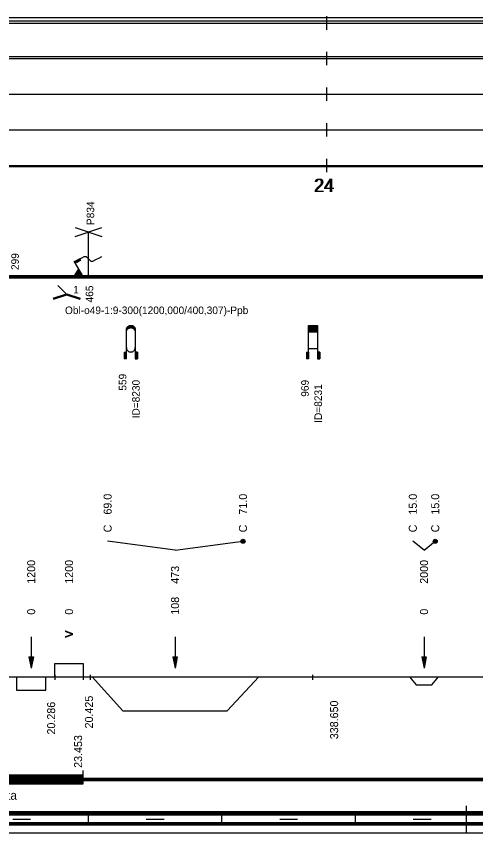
# Model space of a CAD drawing. Extents: x 2 to 10148, y 0 to 380.
# Drawn here: x 2628.8 to 2732, y 0 to 183.5 of the extents above; entities that cross this region are included whole.
import ezdxf

# ---------------------------------------------------------------- set-up
doc = ezdxf.new("R2010")
doc.units = 0
for name, color, linetype in [('CARA_S_OBJEKTY', 7, 'Continuous'), ('KRIV1_CARA', 7, 'Continuous'), ('KRIV1_TEXT', 7, 'Continuous'), ('L_OBJEKTY_TEXT', 7, 'Continuous'), ('L_OBJEKTY_TVAR', 7, 'Continuous'), ('OBJEKTY_TEXT', 7, 'Continuous'), ('OBJEKTY_TVAR', 7, 'Continuous'), ('RAM', 7, 'Continuous'), ('RYCHL_A', 7, 'Continuous'), ('RYCHL_B', 7, 'Continuous'), ('RYCHL_C', 7, 'Continuous'), ('RYCHL_RASTR', 7, 'Continuous'), ('RYCHL_STAN', 7, 'Continuous'), ('STAN_CARA', 7, 'Continuous')]:
    doc.layers.add(name, color=color, linetype=linetype)

msp = doc.modelspace()

# ---------------------------------------------------------------- linework, layer by layer
for p, q in [((2637.43, 35.51), (2637.43, 34.32)), ((2643.79, 35.51), (2643.79, 34.32)), ((2645.42, 35.51), (2645.42, 34.32)), ((2695.33, 35.51), (2695.33, 34.32))]:
    msp.add_line(p, q)
at = {"layer": 'CARA_S_OBJEKTY'}
for p, q in [((2328.7, 125.25), (3155.54, 125.25)), ((2328.7, 125), (3155.54, 125)), ((2328.7, 124.75), (3155.54, 124.75))]:
    msp.add_line(p, q, dxfattribs=at)
at = {"layer": 'KRIV1_CARA'}
for p, q in [((2637.46, 35), (2637.46, 38)), ((2637.46, 38), (2643.81, 38)), ((2643.81, 38), (2643.81, 35)), ((2328.7, 35), (3155.54, 35)), ((2628.83, 35), (2628.83, 32)), ((2635.43, 32), (2635.43, 35)), ((2645.86, 35), (2652.76, 27.39)), ((2676.19, 27.39), (2683.29, 35)), ((2717.16, 35), (2718.66, 33.2)), ((2722.2, 33.2), (2723.7, 35)), ((2718.66, 33.2), (2722.2, 33.2)), ((2628.83, 32), (2635.43, 32)), ((2652.76, 27.39), (2676.19, 27.39))]:
    msp.add_line(p, q, dxfattribs=at)
at = {"layer": 'KRIV1_TEXT'}
for p, q in [((2664.47, 63.5), (2649.31, 65.5)), ((2664.47, 63.5), (2679.74, 65.5)), ((2720.43, 63.5), (2717.91, 65.5)), ((2720.43, 63.5), (2722.95, 65.5)), ((2632.13, 44), (2632.13, 42.2)), ((2664.47, 44), (2664.47, 42.2)), ((2720.43, 44), (2720.43, 42.2)), ((2632.13, 42.2), (2632.13, 40)), ((2664.47, 42.2), (2664.47, 40)), ((2720.43, 42.2), (2720.43, 40)), ((2631.63, 39.5), (2632.13, 37)), ((2631.63, 39.5), (2632.63, 39.5)), ((2631.73, 39.5), (2632.13, 37.5)), ((2631.83, 39.5), (2632.13, 38)), ((2631.93, 39.5), (2632.13, 38.5)), ((2632.03, 39.5), (2632.13, 39)), ((2632.13, 40), (2632.13, 37)), ((2632.63, 39.5), (2632.13, 37)), ((2632.53, 39.5), (2632.13, 37.5)), ((2632.43, 39.5), (2632.13, 38)), ((2632.33, 39.5), (2632.13, 38.5)), ((2632.23, 39.5), (2632.13, 39)), ((2632.13, 39.5), (2632.13, 39.5)), ((2632.13, 39.5), (2632.13, 39.5)), ((2663.97, 39.5), (2664.47, 37)), ((2663.97, 39.5), (2664.97, 39.5)), ((2664.07, 39.5), (2664.47, 37.5)), ((2664.17, 39.5), (2664.47, 38)), ((2664.27, 39.5), (2664.47, 38.5)), ((2664.37, 39.5), (2664.47, 39)), ((2664.47, 40), (2664.47, 37)), ((2664.97, 39.5), (2664.47, 37)), ((2664.87, 39.5), (2664.47, 37.5)), ((2664.77, 39.5), (2664.47, 38)), ((2664.67, 39.5), (2664.47, 38.5)), ((2664.57, 39.5), (2664.47, 39)), ((2664.47, 39.5), (2664.47, 39.5)), ((2664.47, 39.5), (2664.47, 39.5)), ((2719.93, 39.5), (2720.43, 37)), ((2719.93, 39.5), (2720.93, 39.5)), ((2720.03, 39.5), (2720.43, 37.5)), ((2720.13, 39.5), (2720.43, 38)), ((2720.23, 39.5), (2720.43, 38.5)), ((2720.33, 39.5), (2720.43, 39)), ((2720.43, 40), (2720.43, 37)), ((2720.93, 39.5), (2720.43, 37)), ((2720.83, 39.5), (2720.43, 37.5)), ((2720.73, 39.5), (2720.43, 38)), ((2720.63, 39.5), (2720.43, 38.5)), ((2720.53, 39.5), (2720.43, 39)), ((2720.43, 39.5), (2720.43, 39.5)), ((2720.43, 39.5), (2720.43, 39.5))]:
    msp.add_line(p, q, dxfattribs=at)
for centre, radius in [((2679.74, 65.5), 0.45), ((2679.74, 65.5), 0.3), ((2679.74, 65.5), 0.15), ((2722.95, 65.5), 0.45), ((2722.95, 65.5), 0.3), ((2722.95, 65.5), 0.15)]:
    msp.add_circle(centre, radius, dxfattribs=at)
at = {"layer": 'L_OBJEKTY_TVAR'}
for p, q in [((2595.01, 13), (2643.82, 13)), ((2643.82, 11), (2643.82, 14)), ((2595.01, 12.75), (2643.82, 12.75)), ((2595.01, 12.5), (2643.82, 12.5)), ((2595.01, 12.25), (2643.82, 12.25)), ((2595.01, 12), (2643.82, 12)), ((2595.01, 11.75), (2643.82, 11.75)), ((2595.01, 11.5), (2643.82, 11.5)), ((2595.01, 11.25), (2643.82, 11.25)), ((2595.01, 11), (2643.82, 11))]:
    msp.add_line(p, q, dxfattribs=at)
at = {"layer": 'OBJEKTY_TVAR'}
for p, q in [((2642.02, 134), (2648.02, 136)), ((2642.02, 136), (2648.02, 134)), ((2645.02, 125), (2645.02, 135)), ((2643.82, 125), (2641.82, 128.46)), ((2642.02, 128.5), (2643.02, 129)), ((2642.22, 128.1), (2642.02, 128.5)), ((2642.12, 128.3), (2643.12, 128.8)), ((2643.22, 128.6), (2642.22, 128.1)), ((2643.02, 129), (2643.52, 129.25)), ((2643.02, 129), (2643.22, 128.6)), ((2643.52, 129.25), (2644.02, 129.5)), ((2644.02, 129.5), (2644.52, 129.5)), ((2644.52, 129.5), (2645.02, 129)), ((2645.02, 129), (2645.52, 128.5)), ((2645.52, 128.5), (2646.02, 128.5)), ((2646.02, 128.5), (2646.68, 128.83)), ((2646.68, 128.83), (2647.35, 129.17)), ((2647.35, 129.17), (2648.02, 129.5)), ((2641.82, 125), (2642.82, 126.73)), ((2641.97, 125), (2642.89, 126.6)), ((2642.12, 125), (2642.97, 126.47)), ((2642.27, 125), (2643.04, 126.34)), ((2642.42, 125), (2643.12, 126.21)), ((2642.57, 125), (2643.19, 126.08)), ((2642.72, 125), (2643.27, 125.95)), ((2642.87, 125), (2643.34, 125.82)), ((2643.02, 125), (2643.42, 125.69)), ((2643.17, 125), (2643.49, 125.56)), ((2643.32, 125), (2643.57, 125.43)), ((2643.47, 125), (2643.64, 125.3)), ((2643.62, 125), (2643.72, 125.17)), ((2640.11, 121), (2638.11, 123)), ((2637.07, 120.12), (2640.07, 121.12)), ((2640.14, 121.12), (2643.14, 120.12)), ((2637.11, 120), (2640.11, 121)), ((2637.14, 119.89), (2640.14, 120.89)), ((2640.07, 120.89), (2643.07, 119.89)), ((2640.11, 121), (2643.11, 120)), ((2653.79, 113.72), (2653.88, 113.8)), ((2653.87, 113.79), (2655.19, 113.79)), ((2653.88, 113.8), (2654.01, 113.89)), ((2653.93, 113.84), (2655.13, 113.84)), ((2654, 113.89), (2655.06, 113.89)), ((2654.01, 113.89), (2654.14, 113.96)), ((2654.09, 113.94), (2654.97, 113.94)), ((2654.14, 113.96), (2654.17, 113.97)), ((2654.17, 113.97), (2654.29, 114.01)), ((2654.22, 113.99), (2654.84, 113.99)), ((2654.29, 114.01), (2654.43, 114.03)), ((2654.43, 114.03), (2654.54, 114.04)), ((2654.54, 114.04), (2654.67, 114.03)), ((2654.67, 114.03), (2654.8, 114)), ((2654.8, 114), (2654.91, 113.97)), ((2654.91, 113.97), (2655.02, 113.91)), ((2655.02, 113.91), (2655.09, 113.86)), ((2655.09, 113.86), (2655.24, 113.75)), ((2694.49, 106.54), (2694.49, 114.04)), ((2694.49, 114.04), (2696.49, 114.04)), ((2694.49, 113.99), (2696.49, 113.99)), ((2694.49, 113.94), (2696.49, 113.94)), ((2694.49, 113.89), (2696.49, 113.89)), ((2694.49, 113.84), (2696.49, 113.84)), ((2694.49, 113.79), (2696.49, 113.79)), ((2696.49, 114.04), (2696.49, 106.54)), ((2653.53, 113.04), (2653.54, 113.19)), ((2653.53, 113.09), (2653.71, 113.09)), ((2653.53, 106.54), (2653.53, 113.04)), ((2653.53, 113.04), (2653.68, 113.04)), ((2653.53, 112.99), (2653.65, 112.99)), ((2653.53, 112.94), (2653.62, 112.94)), ((2653.53, 112.89), (2653.6, 112.89)), ((2653.53, 112.84), (2653.58, 112.84)), ((2653.53, 112.79), (2653.57, 112.79)), ((2653.53, 112.74), (2653.56, 112.74)), ((2653.53, 112.69), (2653.55, 112.69)), ((2653.53, 112.52), (2653.54, 112.67)), ((2653.53, 112.64), (2653.54, 112.64)), ((2653.54, 113.19), (2653.58, 113.35)), ((2653.54, 113.19), (2653.79, 113.19)), ((2653.54, 113.14), (2653.75, 113.14)), ((2653.54, 112.67), (2653.58, 112.82)), ((2653.55, 113.24), (2653.84, 113.24)), ((2653.56, 113.29), (2653.9, 113.29)), ((2653.58, 113.35), (2653.64, 113.49)), ((2653.58, 113.34), (2653.96, 113.34)), ((2653.58, 112.82), (2653.64, 112.97)), ((2653.59, 113.39), (2654.04, 113.39)), ((2653.61, 113.44), (2654.15, 113.44)), ((2653.64, 113.49), (2653.7, 113.6)), ((2653.64, 113.49), (2654.3, 113.49)), ((2653.64, 112.97), (2653.7, 113.07)), ((2653.66, 113.54), (2655.4, 113.54)), ((2653.69, 113.59), (2655.37, 113.59)), ((2653.7, 113.6), (2653.79, 113.72)), ((2653.7, 113.07), (2653.79, 113.19)), ((2653.73, 113.64), (2655.33, 113.64)), ((2653.77, 113.69), (2655.29, 113.69)), ((2653.79, 113.19), (2653.88, 113.28)), ((2653.82, 113.74), (2655.24, 113.74)), ((2653.88, 113.28), (2654.01, 113.37)), ((2654.01, 113.37), (2654.14, 113.44)), ((2654.14, 113.44), (2654.17, 113.45)), ((2654.17, 113.45), (2654.29, 113.49)), ((2654.29, 113.49), (2654.43, 113.51)), ((2654.43, 113.51), (2654.54, 113.52)), ((2654.54, 113.52), (2654.67, 113.51)), ((2654.67, 113.51), (2654.8, 113.48)), ((2654.76, 113.49), (2655.42, 113.49)), ((2654.8, 113.48), (2654.91, 113.44)), ((2654.91, 113.44), (2655.02, 113.39)), ((2654.91, 113.44), (2655.45, 113.44)), ((2655.02, 113.39), (2655.47, 113.39)), ((2655.02, 113.39), (2655.09, 113.34)), ((2655.09, 113.34), (2655.24, 113.22)), ((2655.1, 113.34), (2655.48, 113.34)), ((2655.16, 113.29), (2655.5, 113.29)), ((2655.22, 113.24), (2655.51, 113.24)), ((2655.24, 113.75), (2655.32, 113.65)), ((2655.24, 113.22), (2655.32, 113.13)), ((2655.27, 113.19), (2655.52, 113.19)), ((2655.31, 113.14), (2655.52, 113.14)), ((2655.32, 113.65), (2655.41, 113.52)), ((2655.32, 113.13), (2655.41, 113)), ((2655.35, 113.09), (2655.53, 113.09)), ((2655.38, 113.04), (2655.53, 113.04)), ((2655.41, 113.52), (2655.45, 113.43)), ((2655.41, 113), (2655.45, 112.91)), ((2655.41, 112.99), (2655.53, 112.99)), ((2655.44, 112.94), (2655.53, 112.94)), ((2655.45, 113.43), (2655.49, 113.31)), ((2655.45, 112.91), (2655.49, 112.78)), ((2655.46, 112.89), (2655.53, 112.89)), ((2655.48, 112.84), (2655.53, 112.84)), ((2655.49, 113.31), (2655.52, 113.19)), ((2655.49, 112.79), (2655.53, 112.79)), ((2655.49, 112.78), (2655.52, 112.67)), ((2655.5, 112.74), (2655.53, 112.74)), ((2655.51, 112.69), (2655.53, 112.69)), ((2655.52, 113.19), (2655.53, 113.1)), ((2655.52, 112.67), (2655.53, 112.57)), ((2655.52, 112.64), (2655.53, 112.64)), ((2655.53, 113.1), (2655.53, 113.04)), ((2655.53, 113.04), (2655.53, 106.54)), ((2655.53, 112.57), (2655.53, 112.52)), ((2694.49, 113.74), (2696.49, 113.74)), ((2694.49, 113.69), (2696.49, 113.69)), ((2694.49, 113.64), (2696.49, 113.64)), ((2694.49, 113.59), (2696.49, 113.59)), ((2694.49, 113.54), (2696.49, 113.54)), ((2694.49, 113.49), (2696.49, 113.49)), ((2694.49, 113.44), (2696.49, 113.44)), ((2694.49, 113.39), (2696.49, 113.39)), ((2694.49, 113.34), (2696.49, 113.34)), ((2694.49, 113.29), (2696.49, 113.29)), ((2694.49, 113.24), (2696.49, 113.24)), ((2694.49, 113.19), (2696.49, 113.19)), ((2694.49, 113.14), (2696.49, 113.14)), ((2694.49, 113.09), (2696.49, 113.09)), ((2694.49, 113.04), (2696.49, 113.04)), ((2694.49, 112.99), (2696.49, 112.99)), ((2694.49, 112.94), (2696.49, 112.94)), ((2694.49, 112.89), (2696.49, 112.89)), ((2694.49, 112.84), (2696.49, 112.84)), ((2694.49, 112.79), (2696.49, 112.79)), ((2694.49, 112.74), (2696.49, 112.74)), ((2694.49, 112.69), (2696.49, 112.69)), ((2694.49, 112.64), (2696.49, 112.64)), ((2694.49, 112.59), (2696.49, 112.59)), ((2653.53, 109.04), (2653.54, 108.89)), ((2653.54, 108.89), (2653.58, 108.74)), ((2653.58, 108.74), (2653.64, 108.59)), ((2653.64, 108.59), (2653.7, 108.49)), ((2653.7, 108.49), (2653.79, 108.37)), ((2653.79, 108.37), (2653.88, 108.28)), ((2653.88, 108.28), (2654.01, 108.19)), ((2655.09, 108.22), (2655.24, 108.34)), ((2655.24, 108.34), (2655.32, 108.44)), ((2655.32, 108.44), (2655.41, 108.56)), ((2655.41, 108.56), (2655.45, 108.65)), ((2655.45, 108.65), (2655.49, 108.78)), ((2655.49, 108.78), (2655.52, 108.89)), ((2655.52, 108.89), (2655.53, 108.99)), ((2655.53, 108.99), (2655.53, 109.04)), ((2694.49, 108.85), (2696.49, 108.85)), ((2653.03, 108.04), (2653.53, 108.04)), ((2653.03, 108.04), (2653.03, 106.54)), ((2653.53, 106.54), (2653.03, 106.54)), ((2653.08, 108.04), (2653.08, 106.54)), ((2653.13, 108.04), (2653.13, 106.54)), ((2653.18, 108.04), (2653.18, 106.54)), ((2653.23, 108.04), (2653.23, 106.54)), ((2653.28, 108.04), (2653.28, 106.54)), ((2653.33, 108.04), (2653.33, 106.54)), ((2653.38, 108.04), (2653.38, 106.54)), ((2653.43, 108.04), (2653.43, 106.54)), ((2653.48, 108.04), (2653.48, 106.54)), ((2654.01, 108.19), (2654.14, 108.12)), ((2654.14, 108.12), (2654.17, 108.11)), ((2654.17, 108.11), (2654.29, 108.07)), ((2654.29, 108.07), (2654.43, 108.05)), ((2654.43, 108.05), (2654.54, 108.04)), ((2654.54, 108.04), (2654.67, 108.05)), ((2654.67, 108.05), (2654.8, 108.08)), ((2654.8, 108.08), (2654.91, 108.12)), ((2654.91, 108.12), (2655.02, 108.17)), ((2655.02, 108.17), (2655.09, 108.22)), ((2656.03, 108.04), (2655.53, 108.04)), ((2655.53, 106.54), (2656.03, 106.54)), ((2655.58, 108.04), (2655.58, 106.54)), ((2655.63, 108.04), (2655.63, 106.54)), ((2655.68, 108.04), (2655.68, 106.54)), ((2655.73, 108.04), (2655.73, 106.54)), ((2655.78, 108.04), (2655.78, 106.54)), ((2655.83, 108.04), (2655.83, 106.54)), ((2655.88, 108.04), (2655.88, 106.54)), ((2655.93, 108.04), (2655.93, 106.54)), ((2655.98, 108.04), (2655.98, 106.54)), ((2656.03, 108.04), (2656.03, 106.54)), ((2693.99, 108.04), (2694.49, 108.04)), ((2693.99, 108.04), (2693.99, 106.54)), ((2694.49, 106.54), (2693.99, 106.54)), ((2694.04, 108.04), (2694.04, 106.54)), ((2694.09, 108.04), (2694.09, 106.54)), ((2694.14, 108.04), (2694.14, 106.54)), ((2694.19, 108.04), (2694.19, 106.54)), ((2694.24, 108.04), (2694.24, 106.54)), ((2694.29, 108.04), (2694.29, 106.54)), ((2694.34, 108.04), (2694.34, 106.54)), ((2694.39, 108.04), (2694.39, 106.54)), ((2694.44, 108.04), (2694.44, 106.54)), ((2696.99, 108.04), (2696.49, 108.04)), ((2696.49, 106.54), (2696.99, 106.54)), ((2696.54, 108.04), (2696.54, 106.54)), ((2696.59, 108.04), (2696.59, 106.54)), ((2696.64, 108.04), (2696.64, 106.54)), ((2696.69, 108.04), (2696.69, 106.54)), ((2696.74, 108.04), (2696.74, 106.54)), ((2696.79, 108.04), (2696.79, 106.54)), ((2696.84, 108.04), (2696.84, 106.54)), ((2696.89, 108.04), (2696.89, 106.54)), ((2696.94, 108.04), (2696.94, 106.54)), ((2696.99, 108.04), (2696.99, 106.54))]:
    msp.add_line(p, q, dxfattribs=at)
at = {"layer": 'RAM'}
for p, q in [((2730, 0), (2730, 6)), ((2328.7, 4.75), (3155.54, 4.75)), ((2328.7, 4.5), (3155.54, 4.5)), ((2328.7, 4.25), (3155.54, 4.25)), ((2328.7, 4), (3155.54, 4)), ((2645, 2), (2645, 4)), ((2675, 2), (2675, 4)), ((2705, 2), (2705, 4)), ((2328.7, 2.25), (3155.54, 2.25)), ((2328.7, 2), (3155.54, 2)), ((2628, 3), (2632, 3)), ((2658, 3), (2662, 3)), ((2688, 3), (2692, 3)), ((2718, 3), (2722, 3)), ((2328.7, 1.75), (3155.54, 1.75)), ((2328.7, 0), (3155.54, 0))]:
    msp.add_line(p, q, dxfattribs=at)
at = {"layer": 'RYCHL_A'}
msp.add_line((2393.05, 174.5), (3156.9, 174.5), dxfattribs=at)
at = {"layer": 'RYCHL_B'}
msp.add_line((2346.36, 182.5), (2815.47, 182.5), dxfattribs=at)
at = {"layer": 'RYCHL_C'}
msp.add_line((2595.01, 183.25), (3155.54, 183.25), dxfattribs=at)
at = {"layer": 'RYCHL_RASTR'}
for p, q in [((2698.55, 180.5), (2698.55, 183.5)), ((2328.7, 182), (3155.54, 182)), ((2698.55, 172.5), (2698.55, 175.5)), ((2328.7, 174), (3155.54, 174)), ((2698.55, 164.5), (2698.55, 167.5)), ((2328.7, 166), (3155.54, 166)), ((2328.7, 158), (3155.54, 158)), ((2698.55, 156.5), (2698.55, 159.5)), ((2698.55, 148.5), (2698.55, 151.5)), ((2328.7, 150), (3155.54, 150)), ((2328.7, 149.75), (3155.54, 149.75))]:
    msp.add_line(p, q, dxfattribs=at)
at = {"layer": 'STAN_CARA'}
for p, q in [((2328.7, 12.25), (2797.05, 12.25)), ((2328.7, 12), (2797.05, 12)), ((2328.7, 12), (2797.05, 12)), ((2328.7, 11.75), (2797.05, 11.75))]:
    msp.add_line(p, q, dxfattribs=at)

# ---------------------------------------------------------------- texts
at = {"layer": 'KRIV1_TEXT'}
for s, p in [('69.0', (2650.21, 71.5)), ('71.0', (2680.64, 71.5)), ('15.0', (2718.81, 71.5)), ('15.0', (2723.85, 71.5)), ('C', (2650.21, 67.5)), ('C', (2680.64, 67.5)), ('C', (2718.81, 67.5)), ('C', (2723.85, 67.5)), ('1200', (2633.03, 55.95)), ('1200', (2641.54, 55.95)), ('2000', (2721.33, 55.95)), ('473', (2665.37, 55.95)), ('108', (2665.37, 49)), ('0', (2633.03, 49)), ('0', (2641.54, 49)), ('0', (2721.33, 49)), ('V', (2641.54, 43.9)), ('V', (2641.54, 43.75)), ('20.425', (2646.01, 23.43)), ('338.650', (2701.13, 21)), ('20.286', (2637.52, 22.06))]:
    msp.add_text(s, height=1.8, rotation=90, dxfattribs=at).set_placement(p)
at = {"layer": 'L_OBJEKTY_TEXT'}
for s, height, p in [('299', 1.7, (2629.35, 126.47)), ('23.453', 1.8, (2643.57, 14.57))]:
    msp.add_text(s, height=height, rotation=90, dxfattribs=at).set_placement(p)
msp.add_text('žst. Zelená Lhota', height=2, dxfattribs=at).set_placement((2608.41, 7.4))
at = {"layer": 'OBJEKTY_TEXT'}
for s, p in [('P834', (2646.29, 136.58)), ('465', (2646.08, 119.19)), ('559', (2653.53, 99.36)), ('ID=8230', (2656.53, 93.13)), ('969', (2694.52, 97.99)), ('ID=8231', (2697.49, 92.13))]:
    msp.add_text(s, height=1.7, rotation=90, dxfattribs=at).set_placement(p)
for s, p in [('1', (2641.59, 121.21)), ('Obl-o49-1:9-300(1200,000/400,307)-Ppb', (2639.73, 116.57))]:
    msp.add_text(s, height=1.7, dxfattribs=at).set_placement(p)
at = {"layer": 'RYCHL_STAN'}
for p in [(2695.61, 144), (2695.86, 144)]:
    msp.add_text('24', height=3, dxfattribs=at).set_placement(p)

doc.saveas('drawing.dxf')
